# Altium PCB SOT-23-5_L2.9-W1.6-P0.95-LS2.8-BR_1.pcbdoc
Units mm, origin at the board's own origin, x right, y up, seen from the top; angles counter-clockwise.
Board outline 16.39 x 16.01 mm, 2 copper layers (Top Layer, Bottom Layer), stack 0 mm thick; 1 components, 0 nets, 5 pads, 0 vias.
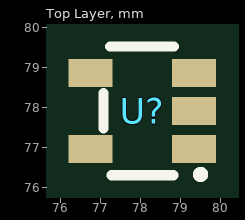
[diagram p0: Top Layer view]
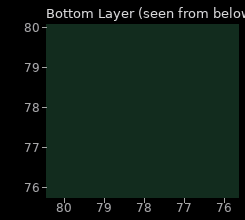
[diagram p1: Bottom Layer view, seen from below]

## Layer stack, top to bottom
Top Layer: signal copper (thickness not stored)
Bottom Layer: signal copper (thickness not stored)

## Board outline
86.238,69.85 69.85,69.85 69.85,85.864 86.238,85.864

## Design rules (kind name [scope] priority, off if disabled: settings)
PasteMaskExpansion "Paste Mask Expansion" [All] p1: expansion=0
SolderMaskExpansion "Solder Mask Expansion" [IsVia] p1: expansion=-25.4 istentingtop=TRUE
SolderMaskExpansion "Solder Mask Expansion" [All] p2: expansion=0.051 istentingtop=FALSE

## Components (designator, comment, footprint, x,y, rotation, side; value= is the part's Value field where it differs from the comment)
U? "" SOT-23-5_L2.9-W1.6-P0.95-LS2.8-BR_1 78.044,77.905 r0 top

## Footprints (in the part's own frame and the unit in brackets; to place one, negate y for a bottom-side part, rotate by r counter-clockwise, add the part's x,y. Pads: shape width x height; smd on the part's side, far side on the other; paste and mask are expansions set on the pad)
SOT-23-5_L2.9-W1.6-P0.95-LS2.8-BR_1 [mm]
  rect 1.1x0.7 smd: 1(1.294,-0.951) 2(1.294,-0.001) 3(1.294,0.951) 4(-1.294,0.951) 5(-1.294,-0.949)
  silkscreen extent -0.97,-1.65 1.52,1.61

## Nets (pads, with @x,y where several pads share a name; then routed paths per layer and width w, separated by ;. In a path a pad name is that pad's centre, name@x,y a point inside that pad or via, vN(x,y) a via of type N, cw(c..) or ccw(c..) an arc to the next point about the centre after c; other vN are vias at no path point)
pads on no net: U?.1 U?.2 U?.3 U?.4 U?.5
